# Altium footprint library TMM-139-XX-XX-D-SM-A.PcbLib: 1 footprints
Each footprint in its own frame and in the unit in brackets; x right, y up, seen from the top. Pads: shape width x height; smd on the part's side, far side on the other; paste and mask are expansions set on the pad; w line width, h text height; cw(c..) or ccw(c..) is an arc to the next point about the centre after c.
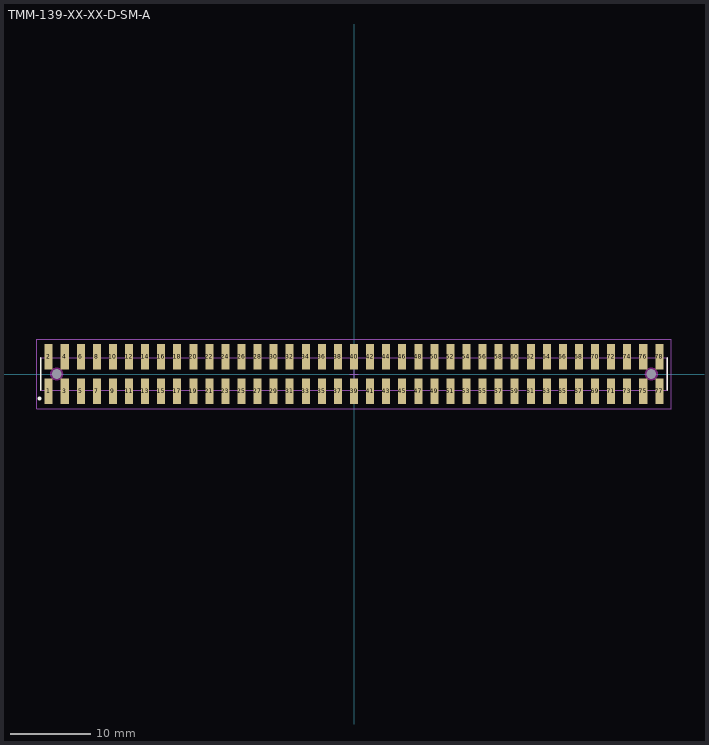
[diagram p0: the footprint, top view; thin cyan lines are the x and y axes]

## TMM-139-XX-XX-D-SM-A [mm] "2.00mm pitch, 78 pin, terminal strip; double row, w/alignment pins, SMT"
height 2.77
pads (80):
  rect 1x3.2 smd mask+0: 1(-38,-2.15) 2(-38,2.15) 3(-36,-2.15) 4(-36,2.15) 5(-34,-2.15) 6(-34,2.15) 7(-32,-2.15) 8(-32,2.15) 9(-30,-2.15) 10(-30,2.15) 11(-28,-2.15) 12(-28,2.15) 13(-26,-2.15) 14(-26,2.15) 15(-24,-2.15) 16(-24,2.15) 17(-22,-2.15) 18(-22,2.15) 19(-20,-2.15) 20(-20,2.15) 21(-18,-2.15) 22(-18,2.15) 23(-16,-2.15) 24(-16,2.15) 25(-14,-2.15) 26(-14,2.15) 27(-12,-2.15) 28(-12,2.15) 29(-10,-2.15) 30(-10,2.15) 31(-8,-2.15) 32(-8,2.15) 33(-6,-2.15) 34(-6,2.15) 35(-4,-2.15) 36(-4,2.15) 37(-2,-2.15) 38(-2,2.15) 39(0,-2.15) 40(0,2.15) 41(2,-2.15) 42(2,2.15) 43(4,-2.15) 44(4,2.15) 45(6,-2.15) 46(6,2.15) 47(8,-2.15) 48(8,2.15) 49(10,-2.15) 50(10,2.15) 51(12,-2.15) 52(12,2.15) 53(14,-2.15) 54(14,2.15) 55(16,-2.15) 56(16,2.15) 57(18,-2.15) 58(18,2.15) 59(20,-2.15) 60(20,2.15) 61(22,-2.15) 62(22,2.15) 63(24,-2.15) 64(24,2.15) 65(26,-2.15) 66(26,2.15) 67(28,-2.15) 68(28,2.15) 69(30,-2.15) 70(30,2.15) 71(32,-2.15) 72(32,2.15) 73(34,-2.15) 74(34,2.15) 75(36,-2.15) 76(36,2.15) 77(38,-2.15) 78(38,2.15)
  round 1 hole 1.2 unplated mask+0: 79(-37,0) 80(37,0)
Top Overlay:
  circle w0.25: c-39.15,-3.05 r0.125
  lines w0.2: -39,-2 -39,2 ; 39,-2 39,2
Keep-Out Layer:
  pour cut-out: 37.807,0 37.779,0.209 37.699,0.403 37.57,0.571 37.403,0.699 37.209,0.779 37,0.807 36.791,0.779 36.596,0.699 36.429,0.571 36.301,0.403 36.22,0.209 36.193,0 36.22,-0.209 36.301,-0.403 36.429,-0.571 36.596,-0.699 36.791,-0.779 37,-0.807 37.209,-0.779 37.403,-0.699 37.57,-0.571 37.699,-0.403 37.779,-0.209
  pour cut-out: -36.193,0 -36.22,0.209 -36.301,0.403 -36.429,0.571 -36.596,0.699 -36.791,0.779 -37,0.807 -37.209,0.779 -37.403,0.699 -37.57,0.571 -37.699,0.403 -37.779,0.209 -37.807,0 -37.779,-0.209 -37.699,-0.403 -37.57,-0.571 -37.403,-0.699 -37.209,-0.779 -37,-0.807 -36.791,-0.779 -36.596,-0.699 -36.429,-0.571 -36.301,-0.403 -36.22,-0.209
Mechanical 12:
  lines w0.001: -39,-2 -39,2 39,2 39,-2 -39,-2
Mechanical 13:
  lines w0.1: -39,-2 -39,2 39,2 39,-2 -39,-2
  text ".Designator" at 0,-0.254 h1.52
Mechanical 15:
  lines w0.05: -0.5,0 0.5,0 ; 0,-0.5 0,0.5 ; -39.5,-4.3 -39.5,4.3 39.5,4.3 39.5,-4.3 -39.5,-4.3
